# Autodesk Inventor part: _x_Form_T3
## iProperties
Created: 2005-11
Part Number: _x_Form_T3
Document SubType Name: Modeling
Designer: IMA/Frank
Manufacturer: Standard
Standards Organization: Custom
Author: IMA/Frank
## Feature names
1. Trennen1
2. Trennen2
3. Trennen3
4. Abgeleiteter Körper1 [Tagging]
